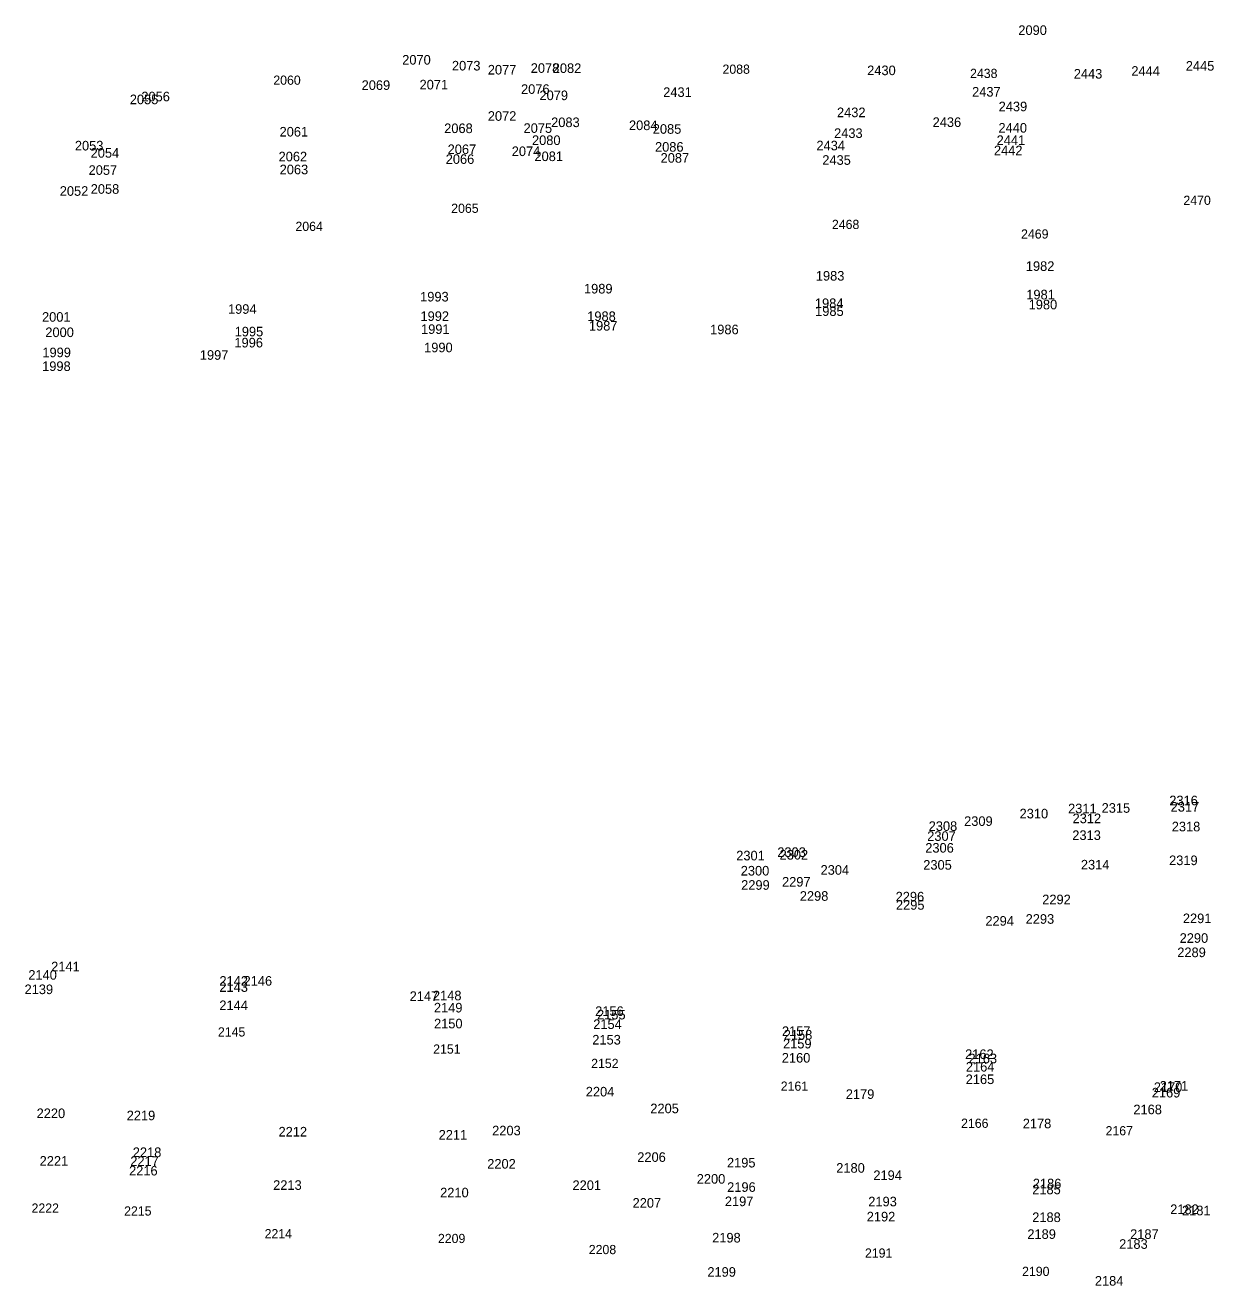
# Model space of a CAD drawing. Extents: x 359002 to 361405, y 1522603 to 1525369.
# Drawn here: x 360526.8 to 360836.7, y 1524608.9 to 1524937.6 of the extents above; entities that cross this region are included whole.
import ezdxf

# ---------------------------------------------------------------- set-up
doc = ezdxf.new("R2010")
doc.units = 0
for name, color, linetype in [('CBS_I', 7, 'Continuous'), ('LABL_I', 7, 'Continuous'), ('LBC_I', 7, 'Continuous'), ('LELB_I', 7, 'Continuous'), ('LELS_I', 7, 'Continuous'), ('LTC_I', 7, 'Continuous'), ('LTD_I', 7, 'Continuous'), ('RDP_I', 7, 'Continuous'), ('RGB_I', 7, 'Continuous'), ('RGW_I', 7, 'Continuous'), ('S_I', 7, 'Continuous'), ('SDEL_I', 7, 'Continuous'), ('SRM_I', 7, 'Continuous'), ('UEO_I', 7, 'Continuous'), ('UFO_I', 7, 'Continuous'), ('ULP_I', 7, 'Continuous'), ('UP_I', 7, 'Continuous'), ('UPGW_I', 7, 'Continuous'), ('UPL_I', 7, 'Continuous')]:
    doc.layers.add(name, color=color, linetype=linetype)

msp = doc.modelspace()

# ---------------------------------------------------------------- texts
at = {"layer": 'CBS_I'}
msp.add_text('2090', height=2.501, dxfattribs=at).set_placement((360785.71, 1524935.01))
at = {"layer": 'LABL_I'}
for s, p in [('2075', (360656.74, 1524909.48)), ('2433', (360737.68, 1524908.16)), ('2057', (360543.36, 1524898.54)), ('1982', (360787.67, 1524873.5)), ('1983', (360732.93, 1524870.97)), ('1993', (360629.78, 1524865.53)), ('1989', (360672.49, 1524867.62)), ('1994', (360579.7, 1524862.31)), ('2001', (360531.22, 1524860.25)), ('2204', (360672.96, 1524658.28)), ('2179', (360740.73, 1524657.64)), ('2205', (360689.78, 1524653.91)), ('2203', (360648.56, 1524648.14)), ('2178', (360786.86, 1524649.98)), ('2202', (360647.27, 1524639.47)), ('2180', (360738.25, 1524638.4)), ('2200', (360701.88, 1524635.54)), ('2201', (360669.5, 1524633.89)), ('2181', (360828.38, 1524627.3))]:
    msp.add_text(s, height=2.501, dxfattribs=at).set_placement(p)
at = {"layer": 'LBC_I'}
for s, p in [('2198', (360705.9, 1524620.21)), ('2199', (360704.65, 1524611.28)), ('2184', (360805.66, 1524608.96))]:
    msp.add_text(s, height=2.501, dxfattribs=at).set_placement(p)
at = {"layer": 'LELB_I'}
for s, p in [('2073', (360638.07, 1524925.75)), ('2077', (360647.42, 1524924.7)), ('2078', (360658.61, 1524925.13)), ('2082', (360664.35, 1524925.1)), ('2076', (360656.08, 1524919.65)), ('2079', (360660.89, 1524918.02)), ('2431', (360693.14, 1524918.85)), ('2439', (360780.58, 1524915.12)), ('2072', (360647.42, 1524912.63)), ('2083', (360663.93, 1524910.99)), ('2432', (360738.44, 1524913.58)), ('2061', (360593.14, 1524908.53)), ('2068', (360636.05, 1524909.43)), ('2075', (360656.74, 1524909.48)), ('2084', (360684.22, 1524910.21)), ('2433', (360737.68, 1524908.16)), ('2440', (360780.53, 1524909.55)), ('2080', (360658.94, 1524906.32)), ('2086', (360691.01, 1524904.58)), ('2434', (360733.08, 1524904.93)), ('2441', (360780.05, 1524906.33)), ('2062', (360592.88, 1524902.06)), ('2066', (360636.45, 1524901.4)), ('2067', (360636.95, 1524903.96)), ('2074', (360653.66, 1524903.44)), ('2081', (360659.58, 1524902.13)), ('2087', (360692.46, 1524901.71)), ('2435', (360734.61, 1524901.16)), ('2442', (360779.35, 1524903.66)), ('2057', (360543.36, 1524898.54)), ('2057', (360543.36, 1524898.54)), ('2063', (360593.16, 1524898.69)), ('2052', (360535.84, 1524893.08)), ('2058', (360543.91, 1524893.61)), ('1981', (360787.78, 1524866.07)), ('1984', (360732.69, 1524863.82)), ('1985', (360732.74, 1524861.76)), ('1980', (360788.4, 1524863.48)), ('1992', (360629.87, 1524860.46)), ('1988', (360673.34, 1524860.43)), ('2000', (360532.08, 1524856.25)), ('1995', (360581.44, 1524856.43)), ('1991', (360630.02, 1524857.07)), ('1987', (360673.78, 1524857.95)), ('1996', (360581.37, 1524853.55)), ('1999', (360531.31, 1524851)), ('2317', (360825.42, 1524732.55)), ('2312', (360799.85, 1524729.52)), ('2318', (360825.7, 1524727.39)), ('2307', (360761.96, 1524724.91)), ('2313', (360799.78, 1524725.14)), ('2303', (360722.88, 1524720.73)), ('2306', (360761.45, 1524721.85)), ('2305', (360760.93, 1524717.4)), ('2314', (360802.02, 1524717.45)), ('2319', (360825.01, 1524718.59)), ('2319', (360825.01, 1524718.59)), ('2300', (360713.35, 1524715.88)), ('2304', (360734.16, 1524716.08)), ('2299', (360713.46, 1524712.16)), ('2297', (360724.12, 1524712.99)), ('2298', (360728.75, 1524709.29)), ('2296', (360753.73, 1524709.12)), ('2295', (360753.81, 1524706.96)), ('2292', (360791.94, 1524708.39)), ('2293', (360787.62, 1524703.3)), ('2291', (360828.6, 1524703.46)), ('2290', (360827.76, 1524698.33)), ('2140', (360527.65, 1524688.72)), ('2139', (360526.67, 1524684.96)), ('2143', (360577.45, 1524685.55)), ('2144', (360577.44, 1524680.79)), ('2149', (360633.37, 1524680.18)), ('2150', (360633.4, 1524676.03)), ('2154', (360674.9, 1524675.86)), ('2153', (360674.65, 1524671.82)), ('2159', (360724.37, 1524670.8)), ('2160', (360724.05, 1524667.11)), ('2164', (360772.04, 1524664.77)), ('2165', (360771.99, 1524661.51)), ('2169', (360820.5, 1524658.02)), ('2220', (360529.81, 1524652.64)), ('2219', (360553.29, 1524652.07)), ('2168', (360815.7, 1524653.65)), ('2212', (360592.87, 1524647.84)), ('2211', (360634.61, 1524647.04)), ('2206', (360686.38, 1524641.22)), ('2206', (360686.38, 1524641.22)), ('2195', (360709.76, 1524639.77)), ('2194', (360747.92, 1524636.49)), ('2196', (360709.81, 1524633.41)), ('2186', (360789.48, 1524634.33)), ('2193', (360746.6, 1524629.63)), ('2188', (360789.33, 1524625.54)), ('2181', (360828.38, 1524627.3)), ('2187', (360814.85, 1524621.15))]:
    msp.add_text(s, height=2.501, dxfattribs=at).set_placement(p)
at = {"layer": 'LELS_I'}
for s, p in [('2088', (360708.6, 1524924.89)), ('2060', (360591.51, 1524922.03)), ('2438', (360773.13, 1524923.79)), ('2065', (360637.88, 1524888.63)), ('2470', (360828.74, 1524890.71)), ('2064', (360597.28, 1524883.92)), ('2468', (360737.12, 1524884.42)), ('2469', (360786.43, 1524881.93)), ('2145', (360577.07, 1524673.91)), ('2151', (360633.18, 1524669.44)), ('2152', (360674.36, 1524665.69)), ('2161', (360723.78, 1524659.77)), ('2166', (360770.79, 1524650.1)), ('2167', (360808.45, 1524648.14)), ('2222', (360528.49, 1524627.98)), ('2215', (360552.62, 1524627.23)), ('2214', (360589.24, 1524621.31)), ('2209', (360634.42, 1524620.06)), ('2208', (360673.74, 1524617.17)), ('2191', (360745.73, 1524616.26)), ('2190', (360786.69, 1524611.48))]:
    msp.add_text(s, height=2.4, dxfattribs=at).set_placement(p)
at = {"layer": 'LTC_I'}
for s, p in [('2444', (360815.17, 1524924.37)), ('2445', (360829.36, 1524925.7)), ('2443', (360800.16, 1524923.63))]:
    msp.add_text(s, height=2.501, dxfattribs=at).set_placement(p)
at = {"layer": 'LTD_I'}
msp.add_text('2430', height=2.501, dxfattribs=at).set_placement((360746.31, 1524924.53))
at = {"layer": 'RDP_I'}
for s, p in [('2055', (360554.1, 1524916.96)), ('2053', (360539.78, 1524904.9)), ('2054', (360543.89, 1524903.01)), ('2221', (360530.6, 1524640.23)), ('2216', (360553.91, 1524637.68)), ('2213', (360591.47, 1524633.93)), ('2210', (360635, 1524631.98)), ('2207', (360685.16, 1524629.28)), ('2197', (360709.21, 1524629.68)), ('2192', (360746.2, 1524625.7)), ('2189', (360788.06, 1524621.15)), ('2183', (360811.99, 1524618.56))]:
    msp.add_text(s, height=2.501, dxfattribs=at).set_placement(p)
at = {"layer": 'RGB_I'}
for s, p in [('2316', (360825.06, 1524734.2)), ('2310', (360786.04, 1524730.77)), ('2311', (360798.68, 1524732.1)), ('2308', (360762.34, 1524727.51)), ('2309', (360771.58, 1524728.81)), ('2303', (360722.88, 1524720.73))]:
    msp.add_text(s, height=2.501, dxfattribs=at).set_placement(p)
at = {"layer": 'RGW_I'}
for s, p in [('2056', (360557.11, 1524917.71)), ('2057', (360543.36, 1524898.54)), ('1990', (360630.82, 1524852.29)), ('1998', (360531.25, 1524847.41)), ('2141', (360533.6, 1524690.9)), ('2146', (360583.76, 1524687.16)), ('2148', (360633.12, 1524683.34)), ('2156', (360675.4, 1524679.27)), ('2157', (360724.09, 1524674.06)), ('2162', (360771.84, 1524668.05)), ('2171', (360822.56, 1524659.8))]:
    msp.add_text(s, height=2.501, dxfattribs=at).set_placement(p)
at = {"layer": 'S_I'}
for s, p in [('2304', (360734.16, 1524716.08)), ('2217', (360554.23, 1524640.18))]:
    msp.add_text(s, height=2.501, dxfattribs=at).set_placement(p)
at = {"layer": 'SDEL_I'}
for s, p in [('1997', (360572.36, 1524850.33)), ('2315', (360807.42, 1524732.24)), ('2302', (360723.48, 1524720.04)), ('2298', (360728.75, 1524709.29)), ('2294', (360777.12, 1524702.8)), ('2289', (360827.14, 1524694.6)), ('2142', (360577.47, 1524687.15)), ('2147', (360627.05, 1524683.18)), ('2155', (360675.89, 1524678.36)), ('2158', (360724.57, 1524673.11)), ('2163', (360772.73, 1524666.93)), ('2170', (360821.02, 1524659.45))]:
    msp.add_text(s, height=2.501, dxfattribs=at).set_placement(p)
at = {"layer": 'SRM_I'}
for s, p in [('1986', (360705.37, 1524856.99)), ('2301', (360712.18, 1524719.82))]:
    msp.add_text(s, height=2.501, dxfattribs=at).set_placement(p)
at = {"layer": 'UEO_I'}
for s, p in [('2070', (360625.11, 1524927.28)), ('2071', (360629.63, 1524920.81)), ('2437', (360773.66, 1524918.95))]:
    msp.add_text(s, height=2.501, dxfattribs=at).set_placement(p)
at = {"layer": 'UFO_I'}
for s, p in [('2185', (360789.33, 1524632.79)), ('2182', (360825.3, 1524627.62))]:
    msp.add_text(s, height=2.501, dxfattribs=at).set_placement(p)
at = {"layer": 'ULP_I'}
msp.add_text('2218', height=2.501, dxfattribs=at).set_placement((360554.88, 1524642.48))
at = {"layer": 'UP_I'}
for s, p in [('2071', (360629.63, 1524920.81)), ('2437', (360773.66, 1524918.95))]:
    msp.add_text(s, height=2.501, dxfattribs=at).set_placement(p)
at = {"layer": 'UPGW_I'}
for s, p in [('2069', (360614.53, 1524920.68)), ('2436', (360763.37, 1524911.03)), ('2085', (360690.42, 1524909.25))]:
    msp.add_text(s, height=2.501, dxfattribs=at).set_placement(p)
at = {"layer": 'UPL_I'}
msp.add_text('2084', height=2.501, dxfattribs=at).set_placement((360684.22, 1524910.21))

doc.saveas('drawing.dxf')
